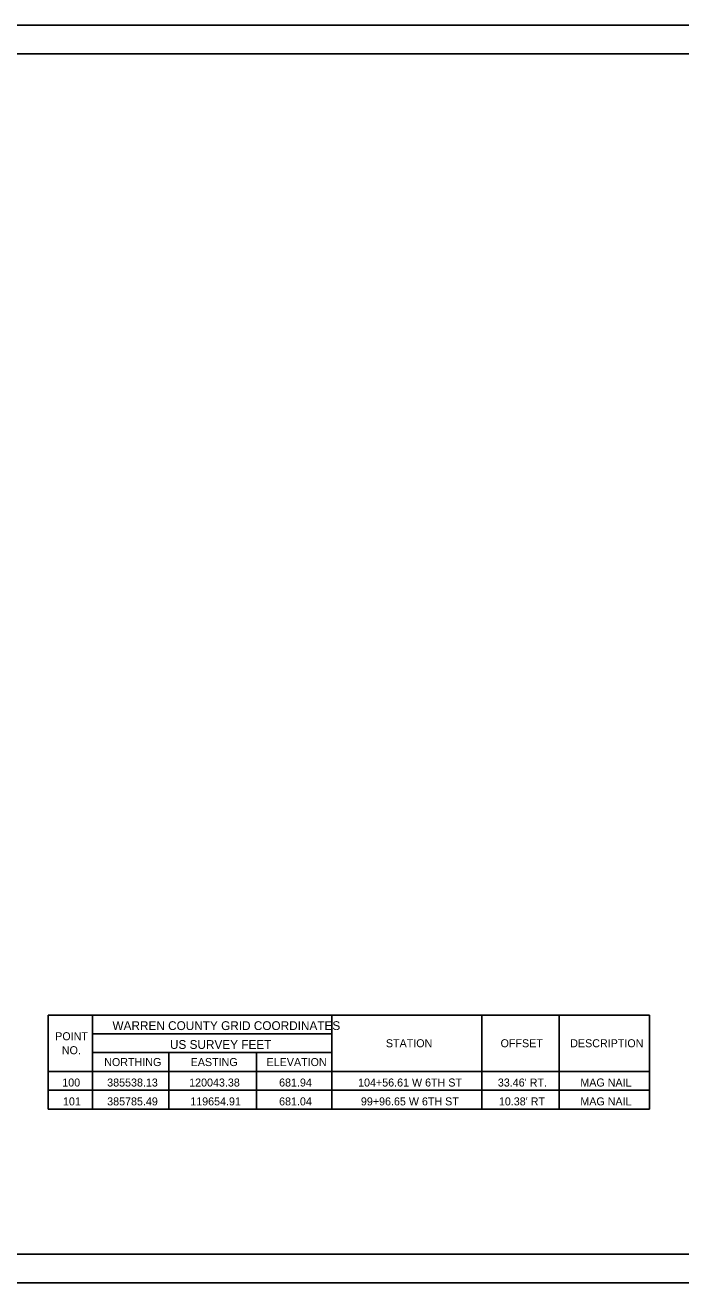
# Model space of a CAD drawing. Extents: x -6.5 to 34, y 0 to 22.
# Drawn here: x 11.08 to 22.54, y 0 to 22 of the extents above; entities that cross this region are included whole.
import ezdxf

# ---------------------------------------------------------------- set-up
doc = ezdxf.new("R2010")
doc.units = 0
for name, color, linetype in [('PM_P_Cells', 7, 'Continuous'), ('PM_X_Cells', 7, 'Continuous'), ('PV_X_EOP', 7, 'Continuous')]:
    doc.layers.add(name, color=color, linetype=linetype)

msp = doc.modelspace()

# ---------------------------------------------------------------- linework, layer by layer
at = {"layer": 'PM_P_Cells'}
msp.add_lwpolyline([(1.5, 21.5), (33.5, 21.5), (33.5, 0.5), (1.5, 0.5)], close=True, dxfattribs=at)
at = {"layer": 'PM_X_Cells'}
msp.add_lwpolyline([(0, 0), (34, 0), (34, 22), (0, 22)], close=True, dxfattribs=at)
at = {"layer": 'PV_X_EOP'}
for p, q in [((11.482, 4.685), (21.99, 4.685)), ((11.482, 4.685), (11.482, 3.038)), ((12.256, 4.685), (12.256, 3.038)), ((16.439, 4.685), (16.439, 3.038)), ((19.058, 4.685), (19.058, 3.038)), ((20.409, 4.685), (20.409, 3.038)), ((21.99, 4.685), (21.99, 3.038)), ((12.256, 4.356), (16.439, 4.356)), ((12.256, 4.027), (16.439, 4.027)), ((13.59, 4.027), (13.59, 3.038)), ((15.122, 4.027), (15.122, 3.038)), ((11.482, 3.697), (21.99, 3.697)), ((11.482, 3.368), (21.99, 3.368)), ((11.482, 3.038), (21.99, 3.038))]:
    msp.add_line(p, q, dxfattribs=at)

# ---------------------------------------------------------------- texts
for s, height, p in [('WARREN COUNTY GRID COORDINATES', 0.154, (12.603, 4.422)), ('POINT ', 0.14, (11.602, 4.244)), ('US SURVEY FEET', 0.154, (13.608, 4.092)), ('STATION', 0.14, (17.383, 4.121)), ('OFFSET', 0.14, (19.388, 4.121)), ('DESCRIPTION', 0.14, (20.605, 4.121)), ('NO.', 0.14, (11.718, 3.999)), ('NORTHING', 0.14, (12.459, 3.792)), ('EASTING', 0.14, (13.97, 3.792)), ('ELEVATION', 0.14, (15.297, 3.792)), ('100', 0.14, (11.726, 3.434)), ('385538.13', 0.14, (12.511, 3.434)), ('120043.38', 0.14, (13.944, 3.434)), ('681.94', 0.14, (15.516, 3.434)), ('104+56.61 W 6TH ST', 0.14, (16.897, 3.434)), ("33.46' RT.", 0.14, (19.34, 3.434)), ('MAG NAIL', 0.14, (20.782, 3.434)), ('101', 0.14, (11.738, 3.104)), ('385785.49', 0.14, (12.511, 3.104)), ('119654.91', 0.14, (13.963, 3.104)), ('681.04', 0.14, (15.516, 3.104)), ('99+96.65 W 6TH ST', 0.14, (16.946, 3.104)), ("10.38' RT", 0.14, (19.358, 3.104)), ('MAG NAIL', 0.14, (20.782, 3.104))]:
    msp.add_text(s, height=height, dxfattribs=at).set_placement(p)

doc.saveas('drawing.dxf')
